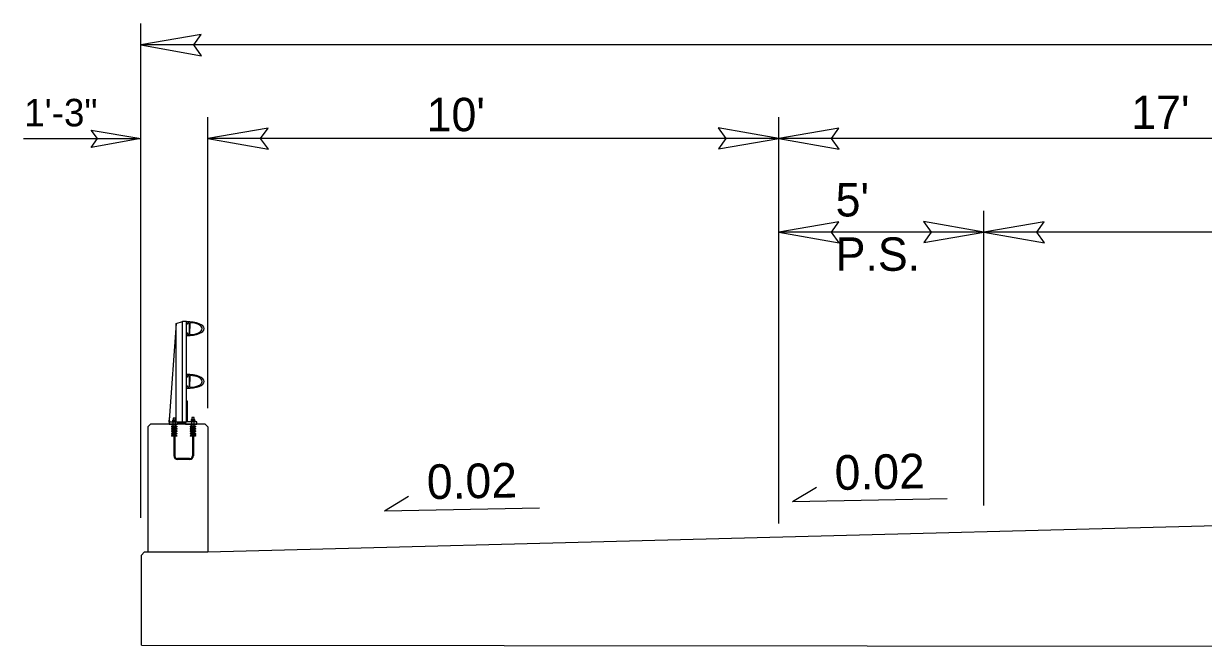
# Model space of a CAD drawing. Extents: x 1733676 to 1734289, y 540979 to 541226.
# Drawn here: x 1733747.61 to 1733769.65, y 541034.32 to 541045.99 of the extents above; entities that cross this region are included whole.
import ezdxf

# ---------------------------------------------------------------- set-up
doc = ezdxf.new("R2010")
doc.units = 0
for name, color, linetype in [('Prop Dimension', 7, 'Continuous'), ('Prop Terminator CELL', 7, 'Continuous'), ('Typical Bridge Rail Two Bar CELL', 7, 'Continuous'), ('Typical Pavement Slope CELL', 7, 'Continuous'), ('Typical Pavement Slope Information CELL', 7, 'Continuous'), ('Typical Slope Point Local CELL', 7, 'Continuous')]:
    doc.layers.add(name, color=color, linetype=linetype)

msp = doc.modelspace()

# ---------------------------------------------------------------- linework, layer by layer
at = {"layer": 'Prop Dimension'}
for p, q in [((1733749.804, 541036.748), (1733749.804, 541045.985)), ((1733794.804, 541045.585), (1733749.804, 541045.585)), ((1733751.054, 541038.795), (1733751.054, 541044.235)), ((1733761.721, 541036.64), (1733761.721, 541044.235)), ((1733747.613, 541043.835), (1733749.804, 541043.835)), ((1733761.721, 541043.835), (1733751.054, 541043.835)), ((1733776.387, 541043.835), (1733760.554, 541043.835)), ((1733765.554, 541036.979), (1733765.554, 541042.485)), ((1733765.554, 541042.085), (1733761.721, 541042.085)), ((1733777.554, 541042.085), (1733765.554, 541042.085))]:
    msp.add_line(p, q, dxfattribs=at)
at = {"layer": 'Prop Terminator CELL'}
for points in [[(1733750.929, 541045.779), (1733749.804, 541045.585), (1733750.935, 541045.385), (1733750.791, 541045.585)], [(1733748.878, 541043.995), (1733749.804, 541043.835), (1733748.873, 541043.671), (1733748.991, 541043.835)], [(1733752.179, 541044.029), (1733751.054, 541043.835), (1733752.185, 541043.635), (1733752.041, 541043.835)], [(1733760.596, 541043.641), (1733761.721, 541043.835), (1733760.589, 541044.035), (1733760.733, 541043.835)], [(1733762.846, 541044.029), (1733761.721, 541043.835), (1733762.852, 541043.635), (1733762.708, 541043.835)], [(1733762.846, 541042.279), (1733761.721, 541042.085), (1733762.852, 541041.885), (1733762.708, 541042.085)], [(1733764.429, 541041.891), (1733765.554, 541042.085), (1733764.423, 541042.285), (1733764.566, 541042.085)], [(1733766.679, 541042.279), (1733765.554, 541042.085), (1733766.685, 541041.885), (1733766.541, 541042.085)]]:
    msp.add_lwpolyline(points, close=True, dxfattribs=at)
at = {"layer": 'Typical Bridge Rail Two Bar CELL'}
for p, q in [((1733750.466, 541040.379), (1733750.334, 541038.571)), ((1733750.466, 541040.379), (1733750.58, 541040.417)), ((1733750.466, 541038.533), (1733750.466, 541040.379)), ((1733750.655, 541040.417), (1733750.58, 541040.417)), ((1733750.58, 541038.533), (1733750.58, 541040.417)), ((1733750.655, 541038.533), (1733750.655, 541040.417)), ((1733750.718, 541040.385), (1733750.718, 541040.283)), ((1733750.718, 541040.181), (1733750.718, 541040.283)), ((1733750.466, 541039.515), (1733750.462, 541039.515)), ((1733750.718, 541039.398), (1733750.718, 541039.296)), ((1733750.718, 541039.194), (1733750.718, 541039.296)), ((1733750.338, 541038.592), (1733750.338, 541038.625)), ((1733750.451, 541038.609), (1733750.408, 541038.609)), ((1733750.408, 541038.609), (1733750.408, 541038.574)), ((1733750.451, 541038.574), (1733750.451, 541038.609)), ((1733750.8, 541038.619), (1733750.756, 541038.619)), ((1733750.756, 541038.619), (1733750.756, 541038.584)), ((1733750.8, 541038.584), (1733750.8, 541038.619)), ((1733749.985, 541038.495), (1733749.936, 541038.447)), ((1733749.936, 541038.447), (1733749.936, 541036.102)), ((1733751.005, 541038.495), (1733749.985, 541038.495)), ((1733750.334, 541038.533), (1733750.334, 541038.571)), ((1733750.478, 541038.459), (1733750.378, 541038.459)), ((1733750.478, 541038.448), (1733750.378, 541038.448)), ((1733750.419, 541038.415), (1733750.378, 541038.415)), ((1733750.419, 541038.404), (1733750.378, 541038.404)), ((1733750.419, 541038.37), (1733750.378, 541038.37)), ((1733750.419, 541038.359), (1733750.378, 541038.359)), ((1733750.419, 541038.437), (1733750.4, 541038.437)), ((1733750.419, 541038.426), (1733750.4, 541038.426)), ((1733750.419, 541038.392), (1733750.4, 541038.392)), ((1733750.419, 541038.381), (1733750.4, 541038.381)), ((1733750.407, 541038.45), (1733750.407, 541038.533)), ((1733750.436, 541038.437), (1733750.419, 541038.437)), ((1733750.419, 541038.437), (1733750.419, 541037.906)), ((1733750.456, 541038.437), (1733750.436, 541038.437)), ((1733750.436, 541038.437), (1733750.436, 541037.906)), ((1733750.456, 541038.426), (1733750.436, 541038.426)), ((1733750.478, 541038.415), (1733750.436, 541038.415)), ((1733750.478, 541038.404), (1733750.436, 541038.404)), ((1733750.456, 541038.392), (1733750.436, 541038.392)), ((1733750.456, 541038.381), (1733750.436, 541038.381)), ((1733750.478, 541038.37), (1733750.436, 541038.37)), ((1733750.478, 541038.359), (1733750.436, 541038.359)), ((1733750.45, 541038.45), (1733750.45, 541038.533)), ((1733750.826, 541038.459), (1733750.726, 541038.459)), ((1733750.826, 541038.448), (1733750.726, 541038.448)), ((1733750.768, 541038.415), (1733750.726, 541038.415)), ((1733750.768, 541038.404), (1733750.726, 541038.404)), ((1733750.768, 541038.37), (1733750.726, 541038.37)), ((1733750.768, 541038.359), (1733750.726, 541038.359)), ((1733750.768, 541038.437), (1733750.749, 541038.437)), ((1733750.768, 541038.426), (1733750.749, 541038.426)), ((1733750.768, 541038.392), (1733750.749, 541038.392)), ((1733750.768, 541038.381), (1733750.749, 541038.381)), ((1733750.754, 541038.459), (1733750.754, 541038.543)), ((1733750.785, 541038.437), (1733750.768, 541038.437)), ((1733750.768, 541038.437), (1733750.768, 541037.906)), ((1733750.804, 541038.437), (1733750.785, 541038.437)), ((1733750.785, 541038.437), (1733750.785, 541037.906)), ((1733750.804, 541038.426), (1733750.785, 541038.426)), ((1733750.826, 541038.415), (1733750.785, 541038.415)), ((1733750.826, 541038.404), (1733750.785, 541038.404)), ((1733750.804, 541038.392), (1733750.785, 541038.392)), ((1733750.804, 541038.381), (1733750.785, 541038.381)), ((1733750.826, 541038.37), (1733750.785, 541038.37)), ((1733750.826, 541038.359), (1733750.785, 541038.359)), ((1733750.802, 541038.459), (1733750.802, 541038.543)), ((1733751.054, 541038.447), (1733751.005, 541038.495)), ((1733751.054, 541038.447), (1733751.054, 541036.102)), ((1733750.419, 541038.326), (1733750.378, 541038.326)), ((1733750.419, 541038.315), (1733750.378, 541038.315)), ((1733750.419, 541038.282), (1733750.378, 541038.282)), ((1733750.419, 541038.271), (1733750.378, 541038.271)), ((1733750.419, 541038.348), (1733750.4, 541038.348)), ((1733750.419, 541038.337), (1733750.4, 541038.337)), ((1733750.419, 541038.304), (1733750.4, 541038.304)), ((1733750.419, 541038.293), (1733750.4, 541038.293)), ((1733750.456, 541038.348), (1733750.436, 541038.348)), ((1733750.456, 541038.337), (1733750.436, 541038.337)), ((1733750.478, 541038.326), (1733750.436, 541038.326)), ((1733750.478, 541038.315), (1733750.436, 541038.315)), ((1733750.456, 541038.304), (1733750.436, 541038.304)), ((1733750.456, 541038.293), (1733750.436, 541038.293)), ((1733750.478, 541038.282), (1733750.436, 541038.282)), ((1733750.478, 541038.271), (1733750.436, 541038.271)), ((1733750.768, 541038.326), (1733750.726, 541038.326)), ((1733750.768, 541038.315), (1733750.726, 541038.315)), ((1733750.768, 541038.282), (1733750.726, 541038.282)), ((1733750.768, 541038.271), (1733750.726, 541038.271)), ((1733750.768, 541038.348), (1733750.749, 541038.348)), ((1733750.768, 541038.337), (1733750.749, 541038.337)), ((1733750.768, 541038.304), (1733750.749, 541038.304)), ((1733750.768, 541038.293), (1733750.749, 541038.293)), ((1733750.804, 541038.348), (1733750.785, 541038.348)), ((1733750.804, 541038.337), (1733750.785, 541038.337)), ((1733750.826, 541038.326), (1733750.785, 541038.326)), ((1733750.826, 541038.315), (1733750.785, 541038.315)), ((1733750.804, 541038.304), (1733750.785, 541038.304)), ((1733750.804, 541038.293), (1733750.785, 541038.293)), ((1733750.826, 541038.282), (1733750.785, 541038.282)), ((1733750.826, 541038.271), (1733750.785, 541038.271)), ((1733750.715, 541037.853), (1733750.49, 541037.853)), ((1733750.715, 541037.837), (1733750.49, 541037.837)), ((1733749.816, 541036.049), (1733749.864, 541036.102)), ((1733749.945, 541036.102), (1733749.864, 541036.102)), ((1733751.054, 541036.102), (1733749.945, 541036.102))]:
    msp.add_line(p, q, dxfattribs=at)
for points in [[(1733750.655, 541040.153), (1733750.655, 541040.202), (1733750.675, 541040.202), (1733750.675, 541040.193), (1733750.673, 541040.193), (1733750.673, 541040.173), (1733750.706, 541040.173), (1733750.71, 541040.204), (1733750.71, 541040.283), (1733750.71, 541040.362), (1733750.706, 541040.393), (1733750.673, 541040.393), (1733750.673, 541040.373), (1733750.675, 541040.373), (1733750.675, 541040.365), (1733750.655, 541040.365), (1733750.655, 541040.414)], [(1733750.655, 541039.165), (1733750.655, 541039.214), (1733750.675, 541039.214), (1733750.675, 541039.206), (1733750.673, 541039.206), (1733750.673, 541039.186), (1733750.706, 541039.186), (1733750.71, 541039.217), (1733750.71, 541039.296), (1733750.71, 541039.375), (1733750.706, 541039.406), (1733750.673, 541039.406), (1733750.673, 541039.386), (1733750.675, 541039.386), (1733750.675, 541039.378), (1733750.655, 541039.378), (1733750.655, 541039.426)], [(1733750.848, 541038.495), (1733750.848, 541038.543), (1733750.674, 541038.543), (1733750.674, 541038.929), (1733750.655, 541038.929), (1733750.655, 541038.533), (1733750.343, 541038.533), (1733750.343, 541038.561), (1733750.334, 541038.561), (1733750.334, 541038.495), (1733750.485, 541038.495), (1733750.485, 541038.522), (1733750.636, 541038.522), (1733750.636, 541038.495), (1733750.848, 541038.495)], [(1733750.81, 541038.551), (1733750.81, 541038.578), (1733750.805, 541038.583), (1733750.751, 541038.583), (1733750.746, 541038.578), (1733750.746, 541038.551), (1733750.81, 541038.551), (1733750.788, 541038.551), (1733750.788, 541038.578), (1733750.794, 541038.583), (1733750.788, 541038.578), (1733750.783, 541038.583), (1733750.772, 541038.583), (1733750.767, 541038.578), (1733750.767, 541038.551), (1733750.767, 541038.578), (1733750.762, 541038.583)], [(1733750.378, 541038.459), (1733750.378, 541038.448), (1733750.4, 541038.437), (1733750.4, 541038.426), (1733750.378, 541038.415), (1733750.378, 541038.404), (1733750.4, 541038.392), (1733750.4, 541038.381), (1733750.378, 541038.37), (1733750.378, 541038.359), (1733750.4, 541038.348), (1733750.4, 541038.337), (1733750.378, 541038.326), (1733750.378, 541038.315), (1733750.4, 541038.304), (1733750.4, 541038.293), (1733750.378, 541038.282), (1733750.378, 541038.271)], [(1733750.472, 541038.533), (1733750.472, 541038.541), (1733750.429, 541038.541), (1733750.386, 541038.541), (1733750.386, 541038.533)], [(1733750.461, 541038.541), (1733750.461, 541038.568), (1733750.455, 541038.574), (1733750.403, 541038.574), (1733750.397, 541038.568), (1733750.397, 541038.541), (1733750.461, 541038.541), (1733750.44, 541038.541), (1733750.44, 541038.568), (1733750.445, 541038.574), (1733750.44, 541038.568), (1733750.435, 541038.574), (1733750.424, 541038.574), (1733750.418, 541038.568), (1733750.418, 541038.541), (1733750.418, 541038.568), (1733750.413, 541038.574)], [(1733750.478, 541038.459), (1733750.478, 541038.448), (1733750.456, 541038.437), (1733750.456, 541038.426), (1733750.478, 541038.415), (1733750.478, 541038.404), (1733750.456, 541038.392), (1733750.456, 541038.381), (1733750.478, 541038.37), (1733750.478, 541038.359), (1733750.456, 541038.348), (1733750.456, 541038.337), (1733750.478, 541038.326), (1733750.478, 541038.315), (1733750.456, 541038.304), (1733750.456, 541038.293), (1733750.478, 541038.282), (1733750.478, 541038.271)], [(1733750.726, 541038.459), (1733750.726, 541038.448), (1733750.749, 541038.437), (1733750.749, 541038.426), (1733750.726, 541038.415), (1733750.726, 541038.404), (1733750.749, 541038.392), (1733750.749, 541038.381), (1733750.726, 541038.37), (1733750.726, 541038.359), (1733750.749, 541038.348), (1733750.749, 541038.337), (1733750.726, 541038.326), (1733750.726, 541038.315), (1733750.749, 541038.304), (1733750.749, 541038.293), (1733750.726, 541038.282), (1733750.726, 541038.271)], [(1733750.822, 541038.542), (1733750.822, 541038.551), (1733750.779, 541038.551), (1733750.735, 541038.551), (1733750.735, 541038.542)], [(1733750.827, 541038.459), (1733750.827, 541038.448), (1733750.804, 541038.437), (1733750.804, 541038.426), (1733750.827, 541038.415), (1733750.827, 541038.404), (1733750.804, 541038.392), (1733750.804, 541038.381), (1733750.827, 541038.37), (1733750.827, 541038.359), (1733750.804, 541038.348), (1733750.804, 541038.337), (1733750.827, 541038.326), (1733750.827, 541038.315), (1733750.804, 541038.304), (1733750.804, 541038.293), (1733750.827, 541038.282), (1733750.827, 541038.271)]]:
    msp.add_lwpolyline(points, dxfattribs=at)
for centre in [(1733750.387, 541038.298), (1733750.818, 541038.298)]:
    msp.add_circle(centre, 0.00834, dxfattribs=at)
for centre, radius, start, end in [((1733750.726, 541040.385), 0.00783, 90, 180), ((1733750.726, 541040.181), 0.00783, 180, 270), ((1733750.726, 541039.398), 0.00783, 90, 180), ((1733750.726, 541039.194), 0.00783, 180, 270), ((1733750.49, 541037.906), 0.07, 180, 270), ((1733750.49, 541037.906), 0.0534, 180, 270), ((1733750.715, 541037.906), 0.0534, 270, 0), ((1733750.715, 541037.906), 0.07, 270, 0)]:
    msp.add_arc(centre, radius, start, end, dxfattribs=at)
for centre, major_axis, ratio, start_param, end_param in [((1733750.655, 541040.283), (0.334, 0), 0.39036, 6.282787, 7.853967), ((1733750.726, 541040.283), (0.222, 0), 0.495501, 6.282718, 7.853881), ((1733750.655, 541040.283), (0.334, 0), 0.39036, 4.712404, 6.282787), ((1733750.726, 541040.283), (0.222, 0), 0.495501, 4.712489, 6.282718), ((1733750.655, 541039.296), (0.334, 0), 0.39036, 6.282787, 7.853967), ((1733750.655, 541039.296), (0.334, 0), 0.39036, 4.712404, 6.282787), ((1733750.726, 541039.296), (0.222, 0), 0.495501, 6.282718, 7.853881), ((1733750.726, 541039.296), (0.222, 0), 0.495501, 4.712489, 6.282718)]:
    msp.add_ellipse(centre, major_axis=major_axis, ratio=ratio, start_param=start_param, end_param=end_param, dxfattribs=at)
at = {"layer": 'Typical Pavement Slope CELL'}
msp.add_line((1733777.554, 541036.801), (1733751.054, 541036.102), dxfattribs=at)
at = {"layer": 'Typical Pavement Slope Information CELL'}
for p, q in [((1733761.975, 541037.05), (1733762.425, 541037.322)), ((1733754.357, 541036.878), (1733754.806, 541037.149)), ((1733761.975, 541037.05), (1733764.87, 541037.108)), ((1733754.357, 541036.878), (1733757.251, 541036.936))]:
    msp.add_line(p, q, dxfattribs=at)
at = {"layer": 'Typical Slope Point Local CELL'}
for q in [(1733749.816, 541036.049), (1733794.804, 541034.324)]:
    msp.add_line((1733749.816, 541034.364), q, dxfattribs=at)

# ---------------------------------------------------------------- texts
at = {"layer": 'Typical Pavement Slope Information CELL'}
for p in [(1733762.771, 541037.267), (1733755.152, 541037.095)]:
    msp.add_text('0.02', height=0.6476, rotation=1.1457, dxfattribs=at).set_placement(p)
at = {"layer": 'Typical Slope Point Local CELL'}
for s, height, p in [('1\'-3"', 0.5141, (1733747.624, 541044.064)), ("10'", 0.6249, (1733755.142, 541043.973)), ("17'", 0.6249, (1733768.306, 541044.016)), (" 5'", 0.6249, (1733762.551, 541042.38)), (' P.S.', 0.6249, (1733762.551, 541041.364))]:
    msp.add_text(s, height=height, rotation=360, dxfattribs=at).set_placement(p)

doc.saveas('drawing.dxf')
